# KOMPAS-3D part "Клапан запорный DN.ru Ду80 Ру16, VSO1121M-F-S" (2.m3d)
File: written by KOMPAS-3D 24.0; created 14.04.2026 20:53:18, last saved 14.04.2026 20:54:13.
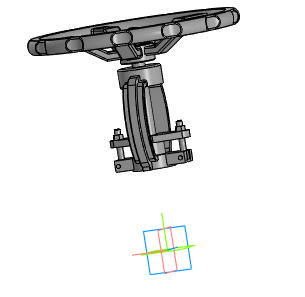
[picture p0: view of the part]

Document properties: Автор: R2D2; Полное имя файла: E:\Работа\Зайцев\VSO3131M-F-S Клапан запорный DN.ru Ду15-100 Ру40\DN80\исходные материалы\2.m3d

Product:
- Part/product: Клапан запорный DN.ru Ду80 Ру16  | designation VSO1121M-F-S
    Масса: 28.77
    Раздел спецификации: Прочие изделия
    Примечание: D090-01949

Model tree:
1. Операция без истории:1
2. Эскиз:1  (with: Грань.Операция без истории:1, Ребро.Операция без истории:1)
3. Элемент выдавливания:1
     Расстояние 2 = 10
4. Эскиз:2  (with: Ребро.Операция без истории:1)
5. Элемент выдавливания:2
     Расстояние 1 = 84
6. Эскиз:3  (with: Ребро.Элемент выдавливания:2, Вершина.Операция без истории:1)
7. Элемент выдавливания:3
     Расстояние 1 = 35
8. Зеркальный массив:1
9. Экземпляр ( 1 )
10. Экземпляр ( 2 )  (with: Элемент выдавливания:3)

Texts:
  VSO1121M-F-S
